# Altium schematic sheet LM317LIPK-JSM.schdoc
size 127 x 101 mm
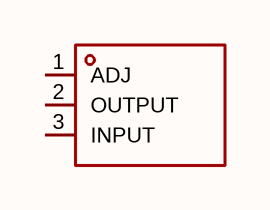
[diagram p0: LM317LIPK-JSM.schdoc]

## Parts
U?  lm317lipk-jsm  [SOT-89-3_L4.5-W2.5-P1.50-LS4.2-BR]  (value not drawn)

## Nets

Not connected (* = marked no-connect by the designer): U? 1(ADJ) 2(OUTPUT) 3(INPUT)

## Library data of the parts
U? = lm317lipk-jsm: 输出极性:正极;工作电压:-;输出电压:1.25V~32V;输出电流:1.5A;电源纹波抑制比(PSRR):75dB@(120Hz);输出类型:可调;; Manufacturer: JSMSEMI(杰盛微); AddInBom: yes; ModelId: 6db690b7897d4d18a30d90c1b89525ee; ModelName: SOT-89-3_L4.3-W2.5-H1.6-LS4.1-P1.50; ModelTransform: 161.417,169.291,0,180,0,0,-18.661,0,0; Output Configuration: 正极; Output Current: 1.5A; Output Type: 可调; Number of Outputs: 1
